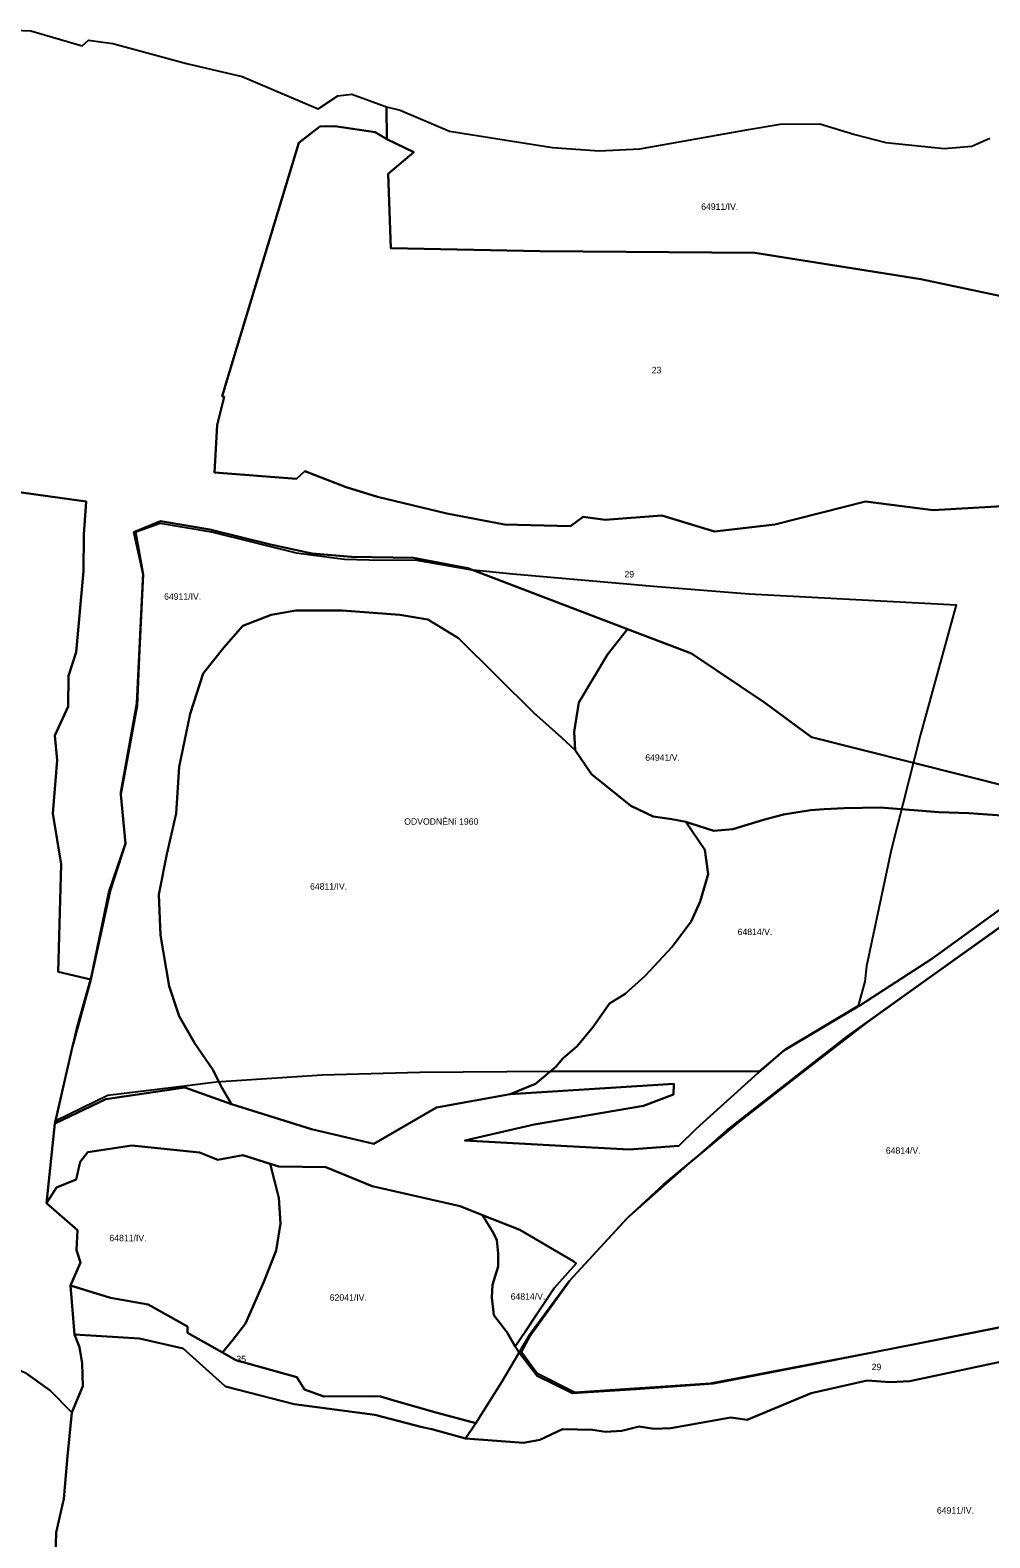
# Model space of a CAD drawing. Extents: x -521621 to -516761, y -1190184 to -1184927.
# Drawn here: x -518679 to -518086, y -1186003 to -1185071 of the extents above; entities that cross this region are included whole.
import ezdxf

# ---------------------------------------------------------------- set-up
doc = ezdxf.new("R2010")
doc.units = 0
doc.layers.add('BPEJ_s', color=7, linetype='Continuous')
doc.layers.add('odvodneni_s', color=7, linetype='Continuous')

msp = doc.modelspace()

# ---------------------------------------------------------------- linework, layer by layer
at = {"layer": 'BPEJ_s'}
for points in [[(-518689.48, -1185070.87), (-518678.95, -1185071.29), (-518647.21, -1185080.53), (-518643.17, -1185077.07), (-518634.51, -1185078.24), (-518628.17, -1185079.09), (-518582.74, -1185091.48), (-518548.39, -1185099.56), (-518501.36, -1185119.48), (-518489.24, -1185111.4), (-518480.58, -1185110.53), (-518459.1, -1185118.33), (-518459.01, -1185138.2), (-518466.24, -1185133.99), (-518491.07, -1185130.18), (-518500.27, -1185130.44), (-518513.41, -1185140.44), (-518551.59, -1185266.93), (-518560.76, -1185296.97), (-518559.45, -1185297.49), (-518563.79, -1185314.98), (-518565.36, -1185344.13), (-518514.77, -1185348.07), (-518509.7, -1185343.33), (-518484.07, -1185353.2), (-518464.83, -1185359.22), (-518421.85, -1185369.48), (-518386.37, -1185376.45), (-518345.59, -1185377.48), (-518337.71, -1185371.69), (-518324.17, -1185373.53), (-518289.03, -1185370.77), (-518256.57, -1185380.76), (-518219.2, -1185376.42), (-518163.22, -1185362.08), (-518121.38, -1185367.48), (-518060.92, -1185363.99)], [(-518076.55, -1185235.78), (-518129, -1185224.7), (-518231.71, -1185208.55), (-518364.33, -1185207.52), (-518456.45, -1185205.68), (-518458.14, -1185159.58), (-518442.24, -1185146.17), (-518459.01, -1185138.2), (-518459.1, -1185118.33), (-518450.74, -1185120.35), (-518420.2, -1185133.31), (-518356.71, -1185143.42), (-518327.86, -1185145.44), (-518302.75, -1185144.29), (-518235.62, -1185132.18), (-518216, -1185129.01), (-518191.46, -1185128.72), (-518169.82, -1185135.36), (-518150.78, -1185140.27), (-518114.63, -1185143.93), (-518097.61, -1185142.49), (-518086.36, -1185137.58)], [(-518060.92, -1185363.99), (-518121.38, -1185367.48), (-518163.22, -1185362.08), (-518219.2, -1185376.42), (-518256.57, -1185380.76), (-518289.03, -1185370.77), (-518324.17, -1185373.53), (-518337.71, -1185371.69), (-518345.59, -1185377.48), (-518386.37, -1185376.45), (-518421.85, -1185369.48), (-518464.83, -1185359.22), (-518484.07, -1185353.2), (-518509.7, -1185343.33), (-518514.77, -1185348.07), (-518565.36, -1185344.13), (-518563.79, -1185314.98), (-518559.45, -1185297.49), (-518560.76, -1185296.97), (-518551.59, -1185266.93), (-518513.41, -1185140.44), (-518500.27, -1185130.44), (-518491.07, -1185130.18), (-518466.24, -1185133.99), (-518459.01, -1185138.2), (-518442.24, -1185146.17), (-518458.14, -1185159.58), (-518456.45, -1185205.68), (-518364.33, -1185207.52), (-518231.71, -1185208.55), (-518129, -1185224.7), (-518076.55, -1185235.78)], [(-518692, -1185355.65), (-518644.75, -1185362.24), (-518646.11, -1185382.49), (-518646.44, -1185405.27), (-518650.86, -1185455.27), (-518653.16, -1185462.22), (-518655.7, -1185469.86), (-518655.86, -1185488.81), (-518663.97, -1185506.8), (-518662.7, -1185522.08), (-518665.4, -1185554.95), (-518660.09, -1185586.25), (-518662.03, -1185652.72), (-518641.9, -1185657.5), (-518653.2, -1185698.94), (-518664.04, -1185746.55), (-518669.14, -1185795.65), (-518650.06, -1185812.42), (-518650.62, -1185824.88), (-518648.2, -1185832.51), (-518654.34, -1185846.65), (-518651.92, -1185876.98), (-518648.85, -1185884.67), (-518647.19, -1185894.85), (-518646.76, -1185908.89), (-518653.56, -1185925.17), (-518666.88, -1185911.56), (-518682.26, -1185900.6)], [(-518041.04, -1185546.97), (-518196.61, -1185507.76), (-518225.54, -1185486.35), (-518270.84, -1185456.12), (-518310.33, -1185441.01), (-518409, -1185403.25), (-518442.55, -1185396.91), (-518480.75, -1185396.32), (-518505.18, -1185394.25), (-518530.85, -1185388.79), (-518568.4, -1185379.51), (-518598.78, -1185374.34), (-518615.3, -1185381.13), (-518609.46, -1185407.21), (-518612.02, -1185458.33), (-518613.29, -1185488.42), (-518623.32, -1185543.2), (-518620.36, -1185573.49), (-518629.78, -1185602.1), (-518641.9, -1185657.5), (-518662.03, -1185652.72), (-518660.09, -1185586.25), (-518665.4, -1185554.95), (-518662.7, -1185522.08), (-518663.97, -1185506.8), (-518655.86, -1185488.81), (-518655.7, -1185469.86), (-518653.16, -1185462.22), (-518650.86, -1185455.27), (-518646.44, -1185405.27), (-518646.11, -1185382.49), (-518644.75, -1185362.24), (-518692, -1185355.65)], [(-518073.24, -1185556.51), (-518099.4, -1185554.77), (-518117.89, -1185554.07), (-518154.16, -1185551.28), (-518176.49, -1185551.63), (-518188.69, -1185552.33), (-518197.22, -1185552.96), (-518213.85, -1185555.57), (-518226.23, -1185558.83), (-518245.14, -1185564.7), (-518256.87, -1185565.68), (-518271.21, -1185561.11), (-518274.15, -1185560.13), (-518282.95, -1185558.5), (-518294.35, -1185556.87), (-518308.17, -1185550.23), (-518332.53, -1185530.61), (-518342.62, -1185515.76), (-518343.18, -1185504.55), (-518340.38, -1185486.33), (-518322.73, -1185456.63), (-518310.33, -1185441.01), (-518270.84, -1185456.12), (-518225.54, -1185486.35), (-518196.61, -1185507.76), (-518041.04, -1185546.97)], [(-518063.02, -1185613.04), (-518124.48, -1185656.9), (-518162.41, -1185684.09), (-518208.81, -1185720.04), (-518241.15, -1185745.28), (-518287.99, -1185784.27), (-518310.01, -1185804.57), (-518346.23, -1185844.02), (-518370.68, -1185876.97), (-518377.14, -1185888.08), (-518379.64, -1185884.41), (-518373.55, -1185875.16), (-518366.29, -1185864.35), (-518355.6, -1185848.26), (-518342.06, -1185833.06), (-518343.52, -1185831.8), (-518376.8, -1185812.27), (-518399.86, -1185803.15), (-518413.63, -1185797.7), (-518468.05, -1185785.21), (-518496.57, -1185773.57), (-518525.71, -1185773.03), (-518530.94, -1185771.41), (-518547.89, -1185766.18), (-518563.38, -1185768.97), (-518574.69, -1185764.36), (-518616.48, -1185760.18), (-518643.78, -1185764.18), (-518648.33, -1185770.12), (-518650.81, -1185781.16), (-518663.08, -1185785.99), (-518669.14, -1185795.65), (-518664.04, -1185746.55), (-518632.46, -1185731.4), (-518583.77, -1185724.21), (-518555.02, -1185734.5), (-518505.45, -1185750.06), (-518466.98, -1185759.04), (-518428.25, -1185736.55), (-518382.84, -1185728.32), (-518281.59, -1185722.02), (-518281.96, -1185728.69), (-518300.47, -1185735.55), (-518368.03, -1185747.22), (-518410.78, -1185757.12), (-518347.62, -1185760.45), (-518309.22, -1185762.57), (-518278.56, -1185760.3), (-518267.94, -1185749.79), (-518229.33, -1185714.91), (-518213.94, -1185701.51), (-518166.65, -1185673.6), (-518122.25, -1185644.81), (-518001.24, -1185557)], [(-518001.24, -1185557), (-518122.25, -1185644.81), (-518166.65, -1185673.6), (-518213.94, -1185701.51), (-518229.33, -1185714.91), (-518267.94, -1185749.79), (-518278.56, -1185760.3), (-518309.22, -1185762.57), (-518347.62, -1185760.45), (-518410.78, -1185757.12), (-518368.03, -1185747.22), (-518300.47, -1185735.55), (-518281.96, -1185728.69), (-518281.59, -1185722.02), (-518382.84, -1185728.32), (-518367.02, -1185722.05), (-518354.64, -1185711.4), (-518350.28, -1185706.34), (-518341.29, -1185698.74), (-518331.51, -1185686.68), (-518321.41, -1185672.33), (-518311.63, -1185666.46), (-518299.57, -1185655.37), (-518282.62, -1185637.43), (-518270.89, -1185621.78), (-518265.35, -1185609.38), (-518260.46, -1185592.42), (-518262.41, -1185577.42), (-518274.15, -1185560.13), (-518271.21, -1185561.11), (-518256.87, -1185565.68), (-518245.14, -1185564.7), (-518226.23, -1185558.83), (-518213.85, -1185555.57), (-518197.22, -1185552.96), (-518188.69, -1185552.33), (-518176.49, -1185551.63), (-518154.16, -1185551.28), (-518117.89, -1185554.07), (-518099.4, -1185554.77), (-518073.24, -1185556.51)], [(-518081.39, -1185872.69), (-518194.51, -1185895.07), (-518257.19, -1185907.14), (-518305.11, -1185910.65), (-518344.17, -1185913.24), (-518366.18, -1185902.4), (-518377.14, -1185888.08), (-518370.68, -1185876.97), (-518346.23, -1185844.02), (-518310.01, -1185804.57), (-518287.99, -1185784.27), (-518241.15, -1185745.28), (-518208.81, -1185720.04), (-518162.41, -1185684.09), (-518124.48, -1185656.9), (-518063.02, -1185613.04)], [(-518052.06, -1185887.84), (-518135.94, -1185905.75), (-518147.92, -1185906.43), (-518162.31, -1185905.31), (-518196.89, -1185913.16), (-518236.33, -1185929.63), (-518246.42, -1185928.13), (-518283.41, -1185934.7), (-518294.05, -1185935.15), (-518303.09, -1185933.79), (-518313.73, -1185936.51), (-518323.91, -1185936.96), (-518331.82, -1185935.83), (-518350.37, -1185935.38), (-518364.4, -1185941.94), (-518374.58, -1185943.75), (-518410.33, -1185941.21), (-518403.92, -1185931.75), (-518387.89, -1185906.24), (-518377.14, -1185888.08), (-518366.18, -1185902.4), (-518344.17, -1185913.24), (-518305.11, -1185910.65), (-518257.19, -1185907.14), (-518194.51, -1185895.07), (-518081.39, -1185872.69)], [(-518663.92, -1186020.8), (-518663.33, -1185999.19), (-518658.59, -1185978.46), (-518656.23, -1185952.11), (-518653.56, -1185925.17), (-518646.76, -1185908.89), (-518647.19, -1185894.85), (-518648.85, -1185884.67), (-518651.92, -1185876.98), (-518611.77, -1185879.41), (-518584.69, -1185885.47), (-518558.58, -1185909.12), (-518516.14, -1185919.93), (-518466.45, -1185926.45), (-518437.16, -1185934.11), (-518431.09, -1185935.46), (-518410.33, -1185941.21), (-518374.58, -1185943.75), (-518364.4, -1185941.94), (-518350.37, -1185935.38), (-518331.82, -1185935.83), (-518323.91, -1185936.96), (-518313.73, -1185936.51), (-518303.09, -1185933.79), (-518294.05, -1185935.15), (-518283.41, -1185934.7), (-518246.42, -1185928.13), (-518236.33, -1185929.63), (-518196.89, -1185913.16), (-518162.31, -1185905.31), (-518147.92, -1185906.43), (-518135.94, -1185905.75), (-518052.06, -1185887.84)], [(-518758.01, -1186004.22), (-518755.34, -1185978.17), (-518749.13, -1185953.59), (-518738.18, -1185920.14), (-518722.8, -1185904.45), (-518704.45, -1185894.98), (-518694.1, -1185895.27), (-518682.26, -1185900.6), (-518666.88, -1185911.56), (-518653.56, -1185925.17), (-518656.23, -1185952.11), (-518658.59, -1185978.46), (-518663.33, -1185999.19), (-518663.92, -1186020.8)]]:
    msp.add_lwpolyline(points, dxfattribs=at)
for points in [[(-518664.04, -1185746.55), (-518653.2, -1185698.94), (-518641.9, -1185657.5), (-518629.78, -1185602.1), (-518620.36, -1185573.49), (-518623.32, -1185543.2), (-518613.29, -1185488.42), (-518612.02, -1185458.33), (-518609.46, -1185407.21), (-518615.3, -1185381.13), (-518598.78, -1185374.34), (-518568.4, -1185379.51), (-518530.85, -1185388.79), (-518505.18, -1185394.25), (-518480.75, -1185396.32), (-518442.55, -1185396.91), (-518409, -1185403.25), (-518310.33, -1185441.01), (-518322.73, -1185456.63), (-518340.38, -1185486.33), (-518343.18, -1185504.55), (-518342.62, -1185515.76), (-518351.02, -1185507.91), (-518368.1, -1185492.78), (-518391.06, -1185470.08), (-518414.59, -1185446.54), (-518433.63, -1185435.05), (-518450.99, -1185432.25), (-518486.56, -1185429.45), (-518515.12, -1185429.45), (-518530.52, -1185432.25), (-518547.89, -1185438.98), (-518559.65, -1185452.43), (-518572.53, -1185468.4), (-518580.37, -1185493.34), (-518587.22, -1185526.14), (-518589.01, -1185555), (-518594.88, -1185580.03), (-518599.73, -1185605.06), (-518598.71, -1185630.08), (-518593.35, -1185661.75), (-518587.22, -1185680.14), (-518577.53, -1185697), (-518566.3, -1185713.6), (-518561.61, -1185723.17), (-518555.02, -1185734.5), (-518583.77, -1185724.21), (-518632.46, -1185731.4)], [(-518555.02, -1185734.5), (-518561.61, -1185723.17), (-518566.3, -1185713.6), (-518577.53, -1185697), (-518587.22, -1185680.14), (-518593.35, -1185661.75), (-518598.71, -1185630.08), (-518599.73, -1185605.06), (-518594.88, -1185580.03), (-518589.01, -1185555), (-518587.22, -1185526.14), (-518580.37, -1185493.34), (-518572.53, -1185468.4), (-518559.65, -1185452.43), (-518547.89, -1185438.98), (-518530.52, -1185432.25), (-518515.12, -1185429.45), (-518486.56, -1185429.45), (-518450.99, -1185432.25), (-518433.63, -1185435.05), (-518414.59, -1185446.54), (-518391.06, -1185470.08), (-518368.1, -1185492.78), (-518351.02, -1185507.91), (-518342.62, -1185515.76), (-518332.53, -1185530.61), (-518308.17, -1185550.23), (-518294.35, -1185556.87), (-518282.95, -1185558.5), (-518274.15, -1185560.13), (-518262.41, -1185577.42), (-518260.46, -1185592.42), (-518265.35, -1185609.38), (-518270.89, -1185621.78), (-518282.62, -1185637.43), (-518299.57, -1185655.37), (-518311.63, -1185666.46), (-518321.41, -1185672.33), (-518331.51, -1185686.68), (-518341.29, -1185698.74), (-518350.28, -1185706.34), (-518354.64, -1185711.4), (-518367.02, -1185722.05), (-518382.84, -1185728.32), (-518428.25, -1185736.55), (-518466.98, -1185759.04), (-518505.45, -1185750.06)], [(-518669.14, -1185795.65), (-518663.08, -1185785.99), (-518650.81, -1185781.16), (-518648.33, -1185770.12), (-518643.78, -1185764.18), (-518616.48, -1185760.18), (-518574.69, -1185764.36), (-518563.38, -1185768.97), (-518547.89, -1185766.18), (-518530.94, -1185771.41), (-518525.67, -1185792.39), (-518524.63, -1185808.39), (-518527.33, -1185825.02), (-518535.02, -1185844.35), (-518546.24, -1185870.12), (-518553.92, -1185880.09), (-518560.48, -1185888.07), (-518582.21, -1185875.78), (-518582.04, -1185871.95), (-518606.39, -1185858.37), (-518629.62, -1185854.28), (-518654.34, -1185846.65), (-518648.2, -1185832.51), (-518650.62, -1185824.88), (-518650.06, -1185812.42)], [(-518560.48, -1185888.07), (-518553.92, -1185880.09), (-518546.24, -1185870.12), (-518535.02, -1185844.35), (-518527.33, -1185825.02), (-518524.63, -1185808.39), (-518525.67, -1185792.39), (-518530.94, -1185771.41), (-518525.71, -1185773.03), (-518496.57, -1185773.57), (-518468.05, -1185785.21), (-518413.63, -1185797.7), (-518399.86, -1185803.15), (-518393.01, -1185814.37), (-518391.09, -1185818.56), (-518390.26, -1185826.85), (-518390.26, -1185834.8), (-518393.77, -1185846.26), (-518394.14, -1185854.02), (-518392.84, -1185864.93), (-518384.72, -1185875.65), (-518379.64, -1185884.41), (-518377.14, -1185888.08), (-518387.89, -1185906.24), (-518403.92, -1185931.75), (-518430.08, -1185924.65), (-518455.22, -1185917.39), (-518462.81, -1185915.19), (-518467.94, -1185915.09), (-518497.91, -1185915.27), (-518509.82, -1185910.8), (-518514.65, -1185903.35), (-518552.25, -1185892.73)], [(-518399.86, -1185803.15), (-518376.8, -1185812.27), (-518343.52, -1185831.8), (-518342.06, -1185833.06), (-518355.6, -1185848.26), (-518366.29, -1185864.35), (-518373.55, -1185875.16), (-518379.64, -1185884.41), (-518384.72, -1185875.65), (-518392.84, -1185864.93), (-518394.14, -1185854.02), (-518393.77, -1185846.26), (-518390.26, -1185834.8), (-518390.26, -1185826.85), (-518391.09, -1185818.56), (-518393.01, -1185814.37)], [(-518654.34, -1185846.65), (-518629.62, -1185854.28), (-518606.39, -1185858.37), (-518582.04, -1185871.95), (-518582.21, -1185875.78), (-518560.48, -1185888.07), (-518552.25, -1185892.73), (-518514.65, -1185903.35), (-518509.82, -1185910.8), (-518497.91, -1185915.27), (-518467.94, -1185915.09), (-518462.81, -1185915.19), (-518455.22, -1185917.39), (-518430.08, -1185924.65), (-518403.92, -1185931.75), (-518410.33, -1185941.21), (-518431.09, -1185935.46), (-518437.16, -1185934.11), (-518466.45, -1185926.45), (-518516.14, -1185919.93), (-518558.58, -1185909.12), (-518584.69, -1185885.47), (-518611.77, -1185879.41), (-518651.92, -1185876.98)]]:
    msp.add_lwpolyline(points, close=True, dxfattribs=at)
at = {"layer": 'odvodneni_s'}
msp.add_lwpolyline([(-518663.37, -1185744.9), (-518650.78, -1185688.33), (-518641.63, -1185656.29), (-518630.67, -1185603.65), (-518620.37, -1185573.58), (-518623.32, -1185541.7), (-518613.35, -1185486.77), (-518609.42, -1185406.18), (-518614, -1185380.84), (-518599.01, -1185375.59), (-518567.38, -1185380.88), (-518515.01, -1185393.9), (-518485.04, -1185397.83), (-518462.19, -1185398.44), (-518441.61, -1185398.29), (-518407.71, -1185404.19), (-518381.08, -1185406.9), (-518294.26, -1185414.53), (-518235.11, -1185419.3), (-518107.27, -1185425.98), (-518129.22, -1185506.12), (-518147.34, -1185577.67), (-518162.61, -1185649.22), (-518163.56, -1185658.76), (-518167.68, -1185673.88), (-518212.93, -1185700.82), (-518229.12, -1185714.44), (-518358.07, -1185714.44), (-518438.58, -1185714.9), (-518498.82, -1185716.71), (-518564.35, -1185720.95), (-518582.36, -1185723.22), (-518631.39, -1185729.28)], close=True, dxfattribs=at)
msp.add_lwpolyline([(-518050.21, -1185866.49), (-518150.32, -1185886.28), (-518259.25, -1185907.12), (-518342.87, -1185912.78), (-518366.07, -1185901), (-518375.83, -1185887.89), (-518370.06, -1185877.13), (-518345.89, -1185843.6), (-518310.65, -1185805.24), (-518249.21, -1185750.82), (-518174.36, -1185692.5), (-518092.02, -1185633.55), (-518034.79, -1185592.7)], dxfattribs=at)

# ---------------------------------------------------------------- texts
at = {"layer": 'BPEJ_s'}
for s, p in [('64911/IV.', (-518264.76, -1185181.91)), ('23', (-518295.35, -1185282.94)), ('29', (-518312.16, -1185409.08)), ('64911/IV.', (-518596.56, -1185422.88)), ('64941/V.', (-518299.29, -1185522.35)), ('64811/IV.', (-518506.4, -1185602.01)), ('64814/V.', (-518242.24, -1185630.07)), ('64814/V.', (-518150.65, -1185765.2)), ('64811/IV.', (-518630.34, -1185819.25)), ('62041/IV.', (-518494.22, -1185856.04)), ('64814/V.', (-518382.47, -1185855.42)), ('35', (-518551.91, -1185894.08)), ('29', (-518159.44, -1185898.94)), ('64911/IV.', (-518119.12, -1185987.59))]:
    msp.add_text(s, height=4, dxfattribs=at).set_placement(p)
at = {"layer": 'odvodneni_s'}
msp.add_text('ODVODNĚNí 1960', height=4, dxfattribs=at).set_placement((-518448.22, -1185561.9))

doc.saveas('drawing.dxf')
